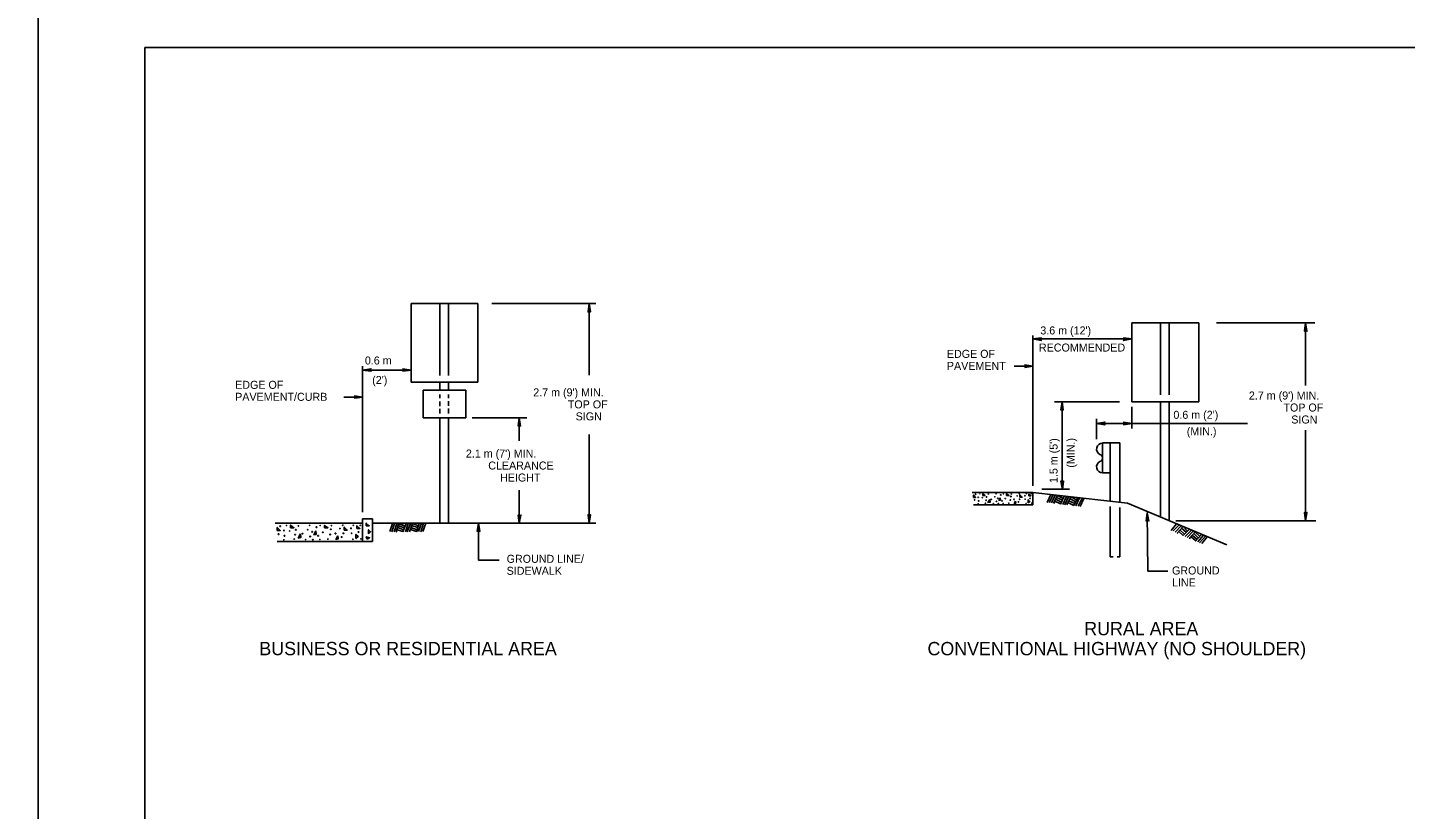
# Model space of a CAD drawing. Extents: x 644358 to 648627, y 294594 to 295782.
# Drawn here: x 646877 to 647394, y 294887 to 295180 of the extents above; entities that cross this region are included whole.
import ezdxf

# ---------------------------------------------------------------- set-up
doc = ezdxf.new("R2010")
doc.units = 0
for name, color, linetype in [('1', 7, 'Continuous'), ('2', 7, 'Continuous'), ('4', 7, 'Continuous'), ('PLT-BNDY', 7, 'Continuous')]:
    doc.layers.add(name, color=color, linetype=linetype)

msp = doc.modelspace()

# ---------------------------------------------------------------- linework, layer by layer
at = {"layer": '1'}
for p, q in [((646921.31, 295172.63), (647707.31, 295172.63)), ((646921.31, 295172.63), (646921.31, 294608.63)), ((647260.94, 295005), (647259.56, 295002)), ((647261.81, 295004.88), (647260.31, 295002)), ((647262.56, 295004.75), (647261.19, 295001.88)), ((647263.44, 295004.75), (647261.94, 295001.75)), ((647264.94, 295002.13), (647262.69, 295003.25)), ((647265.31, 295002.88), (647263.06, 295003.88)), ((647265.56, 295003.5), (647263.44, 295004.63)), ((647265.94, 295004.38), (647264.56, 295001.38)), ((647265.19, 295004.38), (647264.81, 295004.5)), ((647266.81, 295004.25), (647265.44, 295001.25)), ((647267.56, 295004.13), (647266.19, 295001.13)), ((647268.44, 295004.13), (647266.94, 295001.13)), ((647269.94, 295001.63), (647267.69, 295002.63)), ((647270.19, 295002.25), (647268.06, 295003.5)), ((647270.56, 295003), (647268.44, 295004.13)), ((647269.31, 295003.88), (647268.94, 295004.13)), ((647270.94, 295003.75), (647269.56, 295000.88)), ((647271.69, 295003.75), (647270.31, 295000.75)), ((647272.69, 295003.63), (647271.19, 295000.63)), ((647273.31, 295003.5), (647271.94, 295000.5)), ((647262.44, 295001.75), (647262.06, 295001.88)), ((647264.56, 295001.5), (647262.44, 295002.5)), ((647269.56, 295000.88), (647267.31, 295002)), ((647297.31, 294976.25), (647297.06, 294998.13)), ((647014.19, 294994.13), (647013.19, 294991.13)), ((647014.94, 294994.13), (647013.94, 294991)), ((647015.81, 294994.13), (647014.81, 294991)), ((647016.56, 294994.13), (647015.56, 294991)), ((647018.31, 294991.75), (647016.19, 294992.63)), ((647018.69, 294992.5), (647016.44, 294993.25)), ((647018.94, 294993.13), (647016.56, 294994)), ((647018.31, 294994), (647017.94, 294994.13)), ((647019.31, 294994.13), (647018.06, 294991)), ((647020.06, 294994.13), (647019.06, 294991)), ((647020.94, 294994.13), (647019.69, 294991)), ((647021.69, 294994.13), (647020.56, 294991)), ((647023.44, 294991.75), (647021.06, 294992.63)), ((647023.69, 294992.63), (647021.31, 294993.38)), ((647023.94, 294993.25), (647021.69, 294994.13)), ((647022.44, 294994), (647022.19, 294994.25)), ((647024.19, 294994.13), (647023.19, 294991)), ((647025.06, 294994.25), (647023.94, 294991.13)), ((647025.81, 294994.25), (647024.81, 294991)), ((647026.69, 294994.25), (647025.56, 294991.13)), ((647046.44, 294980.38), (647046.44, 294994.25)), ((647308.06, 294994), (647305.94, 294991.5)), ((647308.94, 294993.63), (647306.69, 294991.38)), ((647309.69, 294993.25), (647307.44, 294990.88)), ((647310.44, 294993), (647308.19, 294990.5)), ((647311.69, 294990.75), (647309.81, 294992.5)), ((647312.06, 294991.38), (647310.44, 294993)), ((647015.94, 294991), (647015.56, 294991.13)), ((647018.19, 294991.13), (647015.81, 294991.75)), ((647023.19, 294991.13), (647020.94, 294991.88)), ((647308.56, 294990.38), (647308.31, 294990.63)), ((647310.56, 294989.63), (647308.81, 294991.25)), ((647311.06, 294990.13), (647309.31, 294991.75)), ((647312.69, 294991.88), (647310.56, 294989.63)), ((647313.44, 294991.5), (647311.31, 294989.25)), ((647314.19, 294991.25), (647311.94, 294988.88)), ((647314.94, 294991), (647312.81, 294988.5)), ((647313.19, 294988.5), (647312.81, 294988.63)), ((647315.19, 294987.63), (647313.44, 294989.13)), ((647315.69, 294988.13), (647313.81, 294989.75)), ((647316.19, 294988.63), (647314.44, 294990.38)), ((647316.69, 294989.25), (647314.94, 294990.88)), ((647317.31, 294990), (647315.06, 294987.5)), ((647315.69, 294990.5), (647315.44, 294990.75)), ((647318.06, 294989.75), (647315.94, 294987.25)), ((647318.81, 294989.38), (647316.56, 294986.88)), ((647319.44, 294989.13), (647317.44, 294986.63))]:
    msp.add_line(p, q, dxfattribs=at)
for points in [[(647264.81, 295036.88), (647265.06, 295036.88), (647265.19, 295039.75), (647264.81, 295036.88), (647264.69, 295036.63), (647265.19, 295039.75), (647265.31, 295036.88), (647265.44, 295036.88), (647265.19, 295039.75), (647265.56, 295036.63), (647265.44, 295036.88)], [(647265.56, 295009.88), (647265.44, 295009.75), (647265.31, 295006.88), (647265.56, 295009.88), (647265.69, 295010), (647265.31, 295006.88), (647265.06, 295009.75), (647264.94, 295009.88), (647265.31, 295006.88), (647264.69, 295010), (647264.94, 295009.88)], [(647296.81, 294995.25), (647296.94, 294995.38), (647297.06, 294998.13), (647296.81, 294995.25), (647296.69, 294995), (647297.06, 294998.13), (647297.31, 294995.38), (647297.56, 294995.25), (647297.06, 294998.13), (647297.69, 294995), (647297.56, 294995.25)], [(647046.06, 294991.25), (647046.31, 294991.38), (647046.44, 294994.25), (647046.06, 294991.25), (647045.94, 294991.13), (647046.44, 294994.25), (647046.56, 294991.38), (647046.69, 294991.25), (647046.44, 294994.25), (647046.94, 294991.13), (647046.69, 294991.25)]]:
    msp.add_lwpolyline(points, dxfattribs=at)
for points in [[(647231.94, 295003.88), (647231.94, 295004.75), (647232.69, 295003.88)], [(647235.44, 295004.63), (647235.44, 295005.25), (647236.19, 295004.63)], [(647238.06, 295003.13), (647238.19, 295002.13), (647237.31, 295002)], [(647241.94, 295003.75), (647242.06, 295002.88), (647241.44, 295002.75)], [(647244.31, 295004.63), (647244.31, 295005.25), (647245.19, 295004.63)], [(647249.31, 295004), (647249.31, 295004.88), (647250.19, 295004)], [(647252.44, 295001.88), (647252.44, 295003), (647253.06, 295002.38)], [(647252.69, 295004.5), (647252.69, 295005.13), (647253.44, 295004.5)], [(647247.69, 295002.5), (647247.81, 295001.75), (647247.19, 295001.63)], [(646970.94, 294991.5), (646970.94, 294992.63), (646972.06, 294991.5)], [(646975.94, 294992.5), (646975.94, 294993.5), (646977.19, 294992.5)], [(646988.69, 294992.5), (646988.69, 294993.38), (646989.94, 294992.5)], [(646996.06, 294991.63), (646996.06, 294992.75), (646997.19, 294991.63)], [(647000.81, 294992.25), (647000.81, 294993.25), (647001.94, 294992.25)], [(647004.31, 294993.25), (647004.31, 294994.25), (647005.44, 294993.25)], [(646979.69, 294990.25), (646979.81, 294988.88), (646978.81, 294988.63)], [(646985.44, 294991.38), (646985.56, 294990), (646984.69, 294989.88)], [(646993.69, 294989.5), (646993.81, 294988.38), (646992.94, 294988.13)], [(647000.44, 294988.5), (647000.44, 294990), (647001.31, 294989.25)], [(647004.69, 294988.25), (647004.31, 294989.13), (647005.56, 294988.75)], [(647005.19, 294990.25), (647005.19, 294991.75), (647005.94, 294991)]]:
    msp.add_lwpolyline(points, close=True, dxfattribs=at)
for centre, radius in [((647232.32, 295002.98), 0.0979), ((647232.71, 295005.07), 0.0979), ((647233.72, 295003.94), 0.0979), ((647233.85, 295002.58), 0.0979), ((647234.37, 295005.25), 0.056), ((647235.2, 295003.82), 0.056), ((647236.65, 295002.84), 0.0979), ((647236.79, 295004.1), 0.0979), ((647237.47, 295005.15), 0.056), ((647238.54, 295003.13), 0.0979), ((647239.9, 295004.13), 0.056), ((647240.41, 295005.28), 0.056), ((647241.04, 295003.61), 0.0979), ((647242.16, 295004.82), 0.0979), ((647242.62, 295002.58), 0.0979), ((647243.14, 295005.25), 0.056), ((647243.82, 295003.46), 0.0979), ((647245.72, 295002.89), 0.0979), ((647245.91, 295004.25), 0.0979), ((647246.07, 295005.2), 0.056), ((647247.14, 295003.18), 0.0979), ((647248.28, 295004.46), 0.056), ((647249.01, 295005.33), 0.056), ((647249.19, 295003.21), 0.0979), ((647251.18, 295004.52), 0.0979), ((647251.3, 295003.23), 0.056), ((647251.74, 295005.3), 0.056), ((647253.11, 295003.54), 0.0979), ((647253.58, 295005.27), 0.056), ((647233.68, 295001.52), 0.056), ((647236.39, 295001.72), 0.056), ((647239.37, 295001.57), 0.056), ((647240.52, 295002.39), 0.0979), ((647241.24, 295001.56), 0.0979), ((647243.05, 295001.6), 0.056), ((647245.17, 295001.72), 0.056), ((647248.74, 295002.24), 0.0979), ((647251.65, 295001.65), 0.056), ((647253.77, 295001.77), 0.056), ((646972.04, 294993.11), 0.141), ((646974.42, 294993.37), 0.0806), ((646978.88, 294993.24), 0.0806), ((646983.12, 294993.42), 0.0806), ((646985.64, 294992.76), 0.141), ((646987.06, 294993.37), 0.0806), ((646991.27, 294993.31), 0.0806), ((646994.45, 294992.24), 0.0806), ((646995.51, 294993.49), 0.0806), ((646998.63, 294992.32), 0.141), ((646999.44, 294993.44), 0.0806), ((647002.09, 294993.4), 0.0806), ((646971.47, 294990.12), 0.141), ((646973.49, 294991.49), 0.141), ((646973.43, 294988.01), 0.0806), ((646973.67, 294989.53), 0.141), ((646975.62, 294991.33), 0.0806), ((646977.34, 294988.29), 0.0806), ((646977.7, 294989.91), 0.141), ((646977.91, 294991.73), 0.141), ((646980.43, 294990.32), 0.141), ((646981.62, 294988.07), 0.0806), ((646982.39, 294991.77), 0.0806), ((646983.27, 294989.26), 0.141), ((646984.03, 294991.01), 0.141), ((646984.32, 294988.07), 0.141), ((646986.3, 294989.53), 0.141), ((646986.93, 294988.12), 0.0806), ((646988.03, 294990.81), 0.141), ((646989.97, 294988.29), 0.0806), ((646990.77, 294989.99), 0.141), ((646991.04, 294991.94), 0.141), ((646992.81, 294990.4), 0.141), ((646995.12, 294989.04), 0.141), ((646995.77, 294990.44), 0.141), ((646998.81, 294990.48), 0.0806), ((646999.31, 294988.19), 0.0806), ((647001.41, 294990.92), 0.141), ((647002.35, 294988.36), 0.0806)]:
    msp.add_circle(centre, radius, dxfattribs=at)
at = {"layer": '2'}
for p, q in [((647021.19, 295076.63), (647021.19, 295047.13)), ((647046.19, 295076.63), (647021.19, 295076.63)), ((647031.94, 295076.63), (647031.94, 295049.63)), ((647035.19, 295076.63), (647035.19, 295049.63)), ((647046.19, 295047.13), (647046.19, 295076.63)), ((647291.31, 295069.38), (647291.31, 295039.75)), ((647316.31, 295069.38), (647291.31, 295069.38)), ((647302.06, 295069.38), (647302.06, 295042.38)), ((647305.31, 295069.38), (647305.31, 295042.38)), ((647316.31, 295039.75), (647316.31, 295069.38)), ((647021.19, 295047.13), (647046.19, 295047.13)), ((647025.69, 295044.13), (647041.69, 295044.13)), ((647025.69, 295033.75), (647025.69, 295044.13)), ((647031.94, 295047.13), (647031.94, 295044.13)), ((647035.19, 295047.13), (647035.19, 295044.13)), ((647041.69, 295033.75), (647041.69, 295044.13)), ((647031.94, 295042.5), (647031.94, 295041.13)), ((647031.94, 295039.88), (647031.94, 295038.13)), ((647035.19, 295042.5), (647035.19, 295041.13)), ((647035.19, 295040), (647035.19, 295038.25)), ((647291.31, 295039.75), (647316.31, 295039.75)), ((647302.06, 295039.75), (647302.06, 294996.38)), ((647305.31, 295039.75), (647305.31, 294995.13)), ((647025.69, 295033.75), (647041.69, 295033.75)), ((647031.94, 295037.13), (647031.94, 295035.38)), ((647031.94, 295033.75), (647031.94, 294994.25)), ((647035.19, 295037.25), (647035.19, 295035.38)), ((647035.19, 295033.75), (647035.19, 294994.25)), ((647280.31, 295024.38), (647286.81, 295024.38)), ((647280.31, 295024.38), (647280.31, 295013.13)), ((647283.19, 295024.38), (647283.19, 295002.38)), ((647286.81, 295024.38), (647286.81, 295002)), ((647280.31, 295013.13), (647283.19, 295013.13)), ((647254.19, 295005.75), (647231.44, 295005.75)), ((647254.19, 295005.75), (647254.19, 295001.13)), ((647254.19, 295005.75), (647289.69, 295001.75)), ((647254.19, 295001.13), (647231.94, 295001.13)), ((647283.19, 295000.5), (647283.19, 294981.63)), ((647286.81, 295000.13), (647286.81, 294981.63)), ((647289.69, 295001.75), (647326.81, 294986.13)), ((647002.94, 294994.25), (646970.19, 294994.25)), ((647002.94, 294995.88), (647002.94, 294987.38)), ((647002.94, 294995.88), (647006.69, 294995.88)), ((647006.69, 294995.88), (647006.69, 294987.38)), ((647006.69, 294994.25), (647090.39, 294994.25)), ((647006.69, 294987.38), (646970.94, 294987.38)), ((647283.19, 294981.63), (647284.31, 294981.63)), ((647285.81, 294981.63), (647286.81, 294981.63))]:
    msp.add_line(p, q, dxfattribs=at)
for centre, radius, start, end in [((647280.3, 295022.02), 2.25, 89.9698, 242.4823), ((647278.94, 295018.7), 1.36, 283.7991, 76.2589), ((647280.3, 295015.38), 2.25, 117.4792, 270.0302)]:
    msp.add_arc(centre, radius, start, end, dxfattribs=at)
at = {"layer": '4'}
for p, q in [((647090.39, 295076.63), (647051.4, 295076.63)), ((647087.83, 295076.63), (647087.83, 295049.78)), ((647254.19, 295064.63), (647254.19, 295008.28)), ((647359.86, 295069.38), (647323.03, 295069.38)), ((647356.41, 295069.38), (647356.41, 295045.82)), ((647291.31, 295063.38), (647254.19, 295063.38)), ((647002.94, 295053.13), (647002.94, 294998.38)), ((647021.19, 295051.63), (647002.94, 295051.63)), ((647247.19, 295053.13), (647254.19, 295053.13)), ((646995.94, 295041.5), (647002.94, 295041.5)), ((647286.69, 295039.75), (647262.31, 295039.75)), ((647265.19, 295039.75), (647265.19, 295007)), ((647064.56, 295033.75), (647044.06, 295033.75)), ((647061.69, 295033.75), (647061.69, 295025.1)), ((647291.31, 295037.88), (647291.31, 295029.75)), ((647278.06, 295033.38), (647278.06, 295025.75)), ((647334.64, 295031.63), (647278.06, 295031.63)), ((647356.41, 294995.13), (647356.41, 295029.17)), ((647087.83, 294994.25), (647087.83, 295027.54)), ((647061.69, 295006.63), (647061.69, 294994.25)), ((647267.94, 295007), (647257.5, 295007)), ((647360.25, 294995.13), (647307.75, 294995.13)), ((647046.44, 294980.38), (647054.19, 294980.38)), ((647297.31, 294976.25), (647304.69, 294976.25))]:
    msp.add_line(p, q, dxfattribs=at)
for points in [[(647087.58, 295073.63), (647087.71, 295073.75), (647087.83, 295076.63), (647087.58, 295073.63), (647087.46, 295073.5), (647087.83, 295076.63), (647087.96, 295073.75), (647088.21, 295073.63), (647087.83, 295076.63), (647088.33, 295073.5), (647088.21, 295073.63)], [(647356.16, 295066.38), (647356.28, 295066.5), (647356.41, 295069.38), (647356.16, 295066.38), (647356.03, 295066.25), (647356.41, 295069.38), (647356.53, 295066.5), (647356.78, 295066.38), (647356.41, 295069.38), (647356.91, 295066.25), (647356.78, 295066.38)], [(647257.19, 295062.88), (647257.06, 295063.13), (647254.19, 295063.38), (647257.19, 295062.88), (647257.31, 295062.75), (647254.19, 295063.38), (647257.06, 295063.5), (647257.19, 295063.63), (647254.19, 295063.38), (647257.31, 295063.75), (647257.19, 295063.63)], [(647288.31, 295063.63), (647288.44, 295063.5), (647291.31, 295063.38), (647288.31, 295063.63), (647288.19, 295063.75), (647291.31, 295063.38), (647288.44, 295063.13), (647288.31, 295063), (647291.31, 295063.38), (647288.19, 295062.75), (647288.31, 295063)], [(647005.94, 295051.38), (647005.94, 295051.63), (647002.94, 295051.63), (647005.94, 295051.38), (647006.06, 295051.25), (647002.94, 295051.63), (647005.94, 295051.75), (647005.94, 295052), (647002.94, 295051.63), (647006.06, 295052.13), (647005.94, 295052)], [(647018.19, 295052), (647018.31, 295051.75), (647021.19, 295051.63), (647018.19, 295052), (647018.06, 295052.13), (647021.19, 295051.63), (647018.31, 295051.63), (647018.19, 295051.38), (647021.19, 295051.63), (647018.06, 295051.25), (647018.19, 295051.38)], [(647251.31, 295053.5), (647251.44, 295053.25), (647254.19, 295053.13), (647251.31, 295053.5), (647251.19, 295053.63), (647254.19, 295053.13), (647251.44, 295053), (647251.31, 295052.75), (647254.19, 295053.13), (647251.19, 295052.63), (647251.31, 295052.75)], [(647000.06, 295041.88), (647000.19, 295041.63), (647002.94, 295041.5), (647000.06, 295041.88), (646999.94, 295042), (647002.94, 295041.5), (647000.19, 295041.38), (647000.06, 295041.13), (647002.94, 295041.5), (646999.94, 295041.13), (647000.06, 295041.13)], [(647061.44, 295030.75), (647061.56, 295030.88), (647061.69, 295033.75), (647061.44, 295030.75), (647061.31, 295030.63), (647061.69, 295033.75), (647061.81, 295030.88), (647062.06, 295030.75), (647061.69, 295033.75), (647062.19, 295030.63), (647062.06, 295030.75)], [(647280.94, 295031.25), (647280.81, 295031.5), (647278.06, 295031.63), (647280.94, 295031.25), (647281.19, 295031.13), (647278.06, 295031.63), (647280.81, 295031.75), (647280.94, 295032), (647278.06, 295031.63), (647281.19, 295032.13), (647280.94, 295032)], [(647288.31, 295032), (647288.44, 295031.75), (647291.31, 295031.63), (647288.31, 295032), (647288.19, 295032.13), (647291.31, 295031.63), (647288.44, 295031.5), (647288.31, 295031.25), (647291.31, 295031.63), (647288.19, 295031.13), (647288.31, 295031.25)], [(647356.16, 294998.13), (647356.28, 294998), (647356.41, 294995.13), (647356.16, 294998.13), (647356.03, 294998.25), (647356.41, 294995.13), (647356.53, 294998), (647356.78, 294998.13), (647356.41, 294995.13), (647356.91, 294998.25), (647356.78, 294998.13)], [(647062.06, 294997.13), (647061.94, 294997), (647061.69, 294994.25), (647062.06, 294997.13), (647062.31, 294997.25), (647061.69, 294994.25), (647061.56, 294997), (647061.44, 294997.13), (647061.69, 294994.25), (647061.31, 294997.25), (647061.44, 294997.13)], [(647087.58, 294997.25), (647087.71, 294997.13), (647087.83, 294994.25), (647087.58, 294997.25), (647087.46, 294997.38), (647087.83, 294994.25), (647087.96, 294997.13), (647088.21, 294997.25), (647087.83, 294994.25), (647088.33, 294997.38), (647088.21, 294997.25)]]:
    msp.add_lwpolyline(points, dxfattribs=at)
at = {"layer": 'PLT-BNDY'}
for points in [[(646040.31, 295187.63), (646881.31, 295187.63), (646881.31, 294593.63), (646040.31, 294593.63)], [(646881.31, 295187.63), (647722.31, 295187.63), (647722.31, 294593.63), (646881.31, 294593.63)]]:
    msp.add_lwpolyline(points, close=True, dxfattribs=at)

# ---------------------------------------------------------------- texts
at = {"layer": '1'}
for s, p in [("3.6 m (12')", (647256.96, 295065.03)), ('RECOMMENDED', (647256.44, 295058.61)), ('0.6 m', (647003.81, 295053.76)), ('EDGE OF', (647221.94, 295056.25)), ('PAVEMENT', (647221.94, 295051.75)), ("(2')", (647006.55, 295046.46)), ('EDGE OF', (646955.19, 295044.63)), ("2.7 m (9') MIN.", (647066.92, 295041.8)), ('PAVEMENT/CURB', (646955.19, 295040.13)), ('TOP OF', (647079.87, 295037.3)), ("2.7 m (9') MIN.", (647335.13, 295040.62)), ('TOP OF', (647348.08, 295036.12)), ('SIGN', (647082.8, 295032.8)), ("0.6 m (2')", (647306.84, 295033.39)), ('SIGN', (647351.01, 295031.62)), ("2.1 m (7') MIN.", (647041.67, 295018.86)), ('CLEARANCE', (647050.05, 295014.36)), ('HEIGHT', (647054.48, 295009.86)), ('GROUND LINE/', (647056.94, 294979.38)), ('SIDEWALK', (647056.94, 294974.88)), ('GROUND', (647306.31, 294975)), ('LINE', (647306.31, 294970.5))]:
    msp.add_text(s, height=3, dxfattribs=at).set_placement(p)
for s, p in [("1.5 m (5')", (647263.44, 295009.29)), ('(MIN.)', (647269.87, 295015.06))]:
    msp.add_text(s, height=3, rotation=90, dxfattribs=at).set_placement(p)
at = {"layer": '2'}
for s, height, p in [('(MIN.)', 3, (647311.85, 295027.2)), ('RURAL AREA', 5, (647273.43, 294952.2)), ('BUSINESS OR RESIDENTIAL AREA', 5, (646964.26, 294944.72)), ('CONVENTIONAL HIGHWAY (NO SHOULDER)', 5, (647214.67, 294944.7))]:
    msp.add_text(s, height=height, dxfattribs=at).set_placement(p)

doc.saveas('drawing.dxf')
